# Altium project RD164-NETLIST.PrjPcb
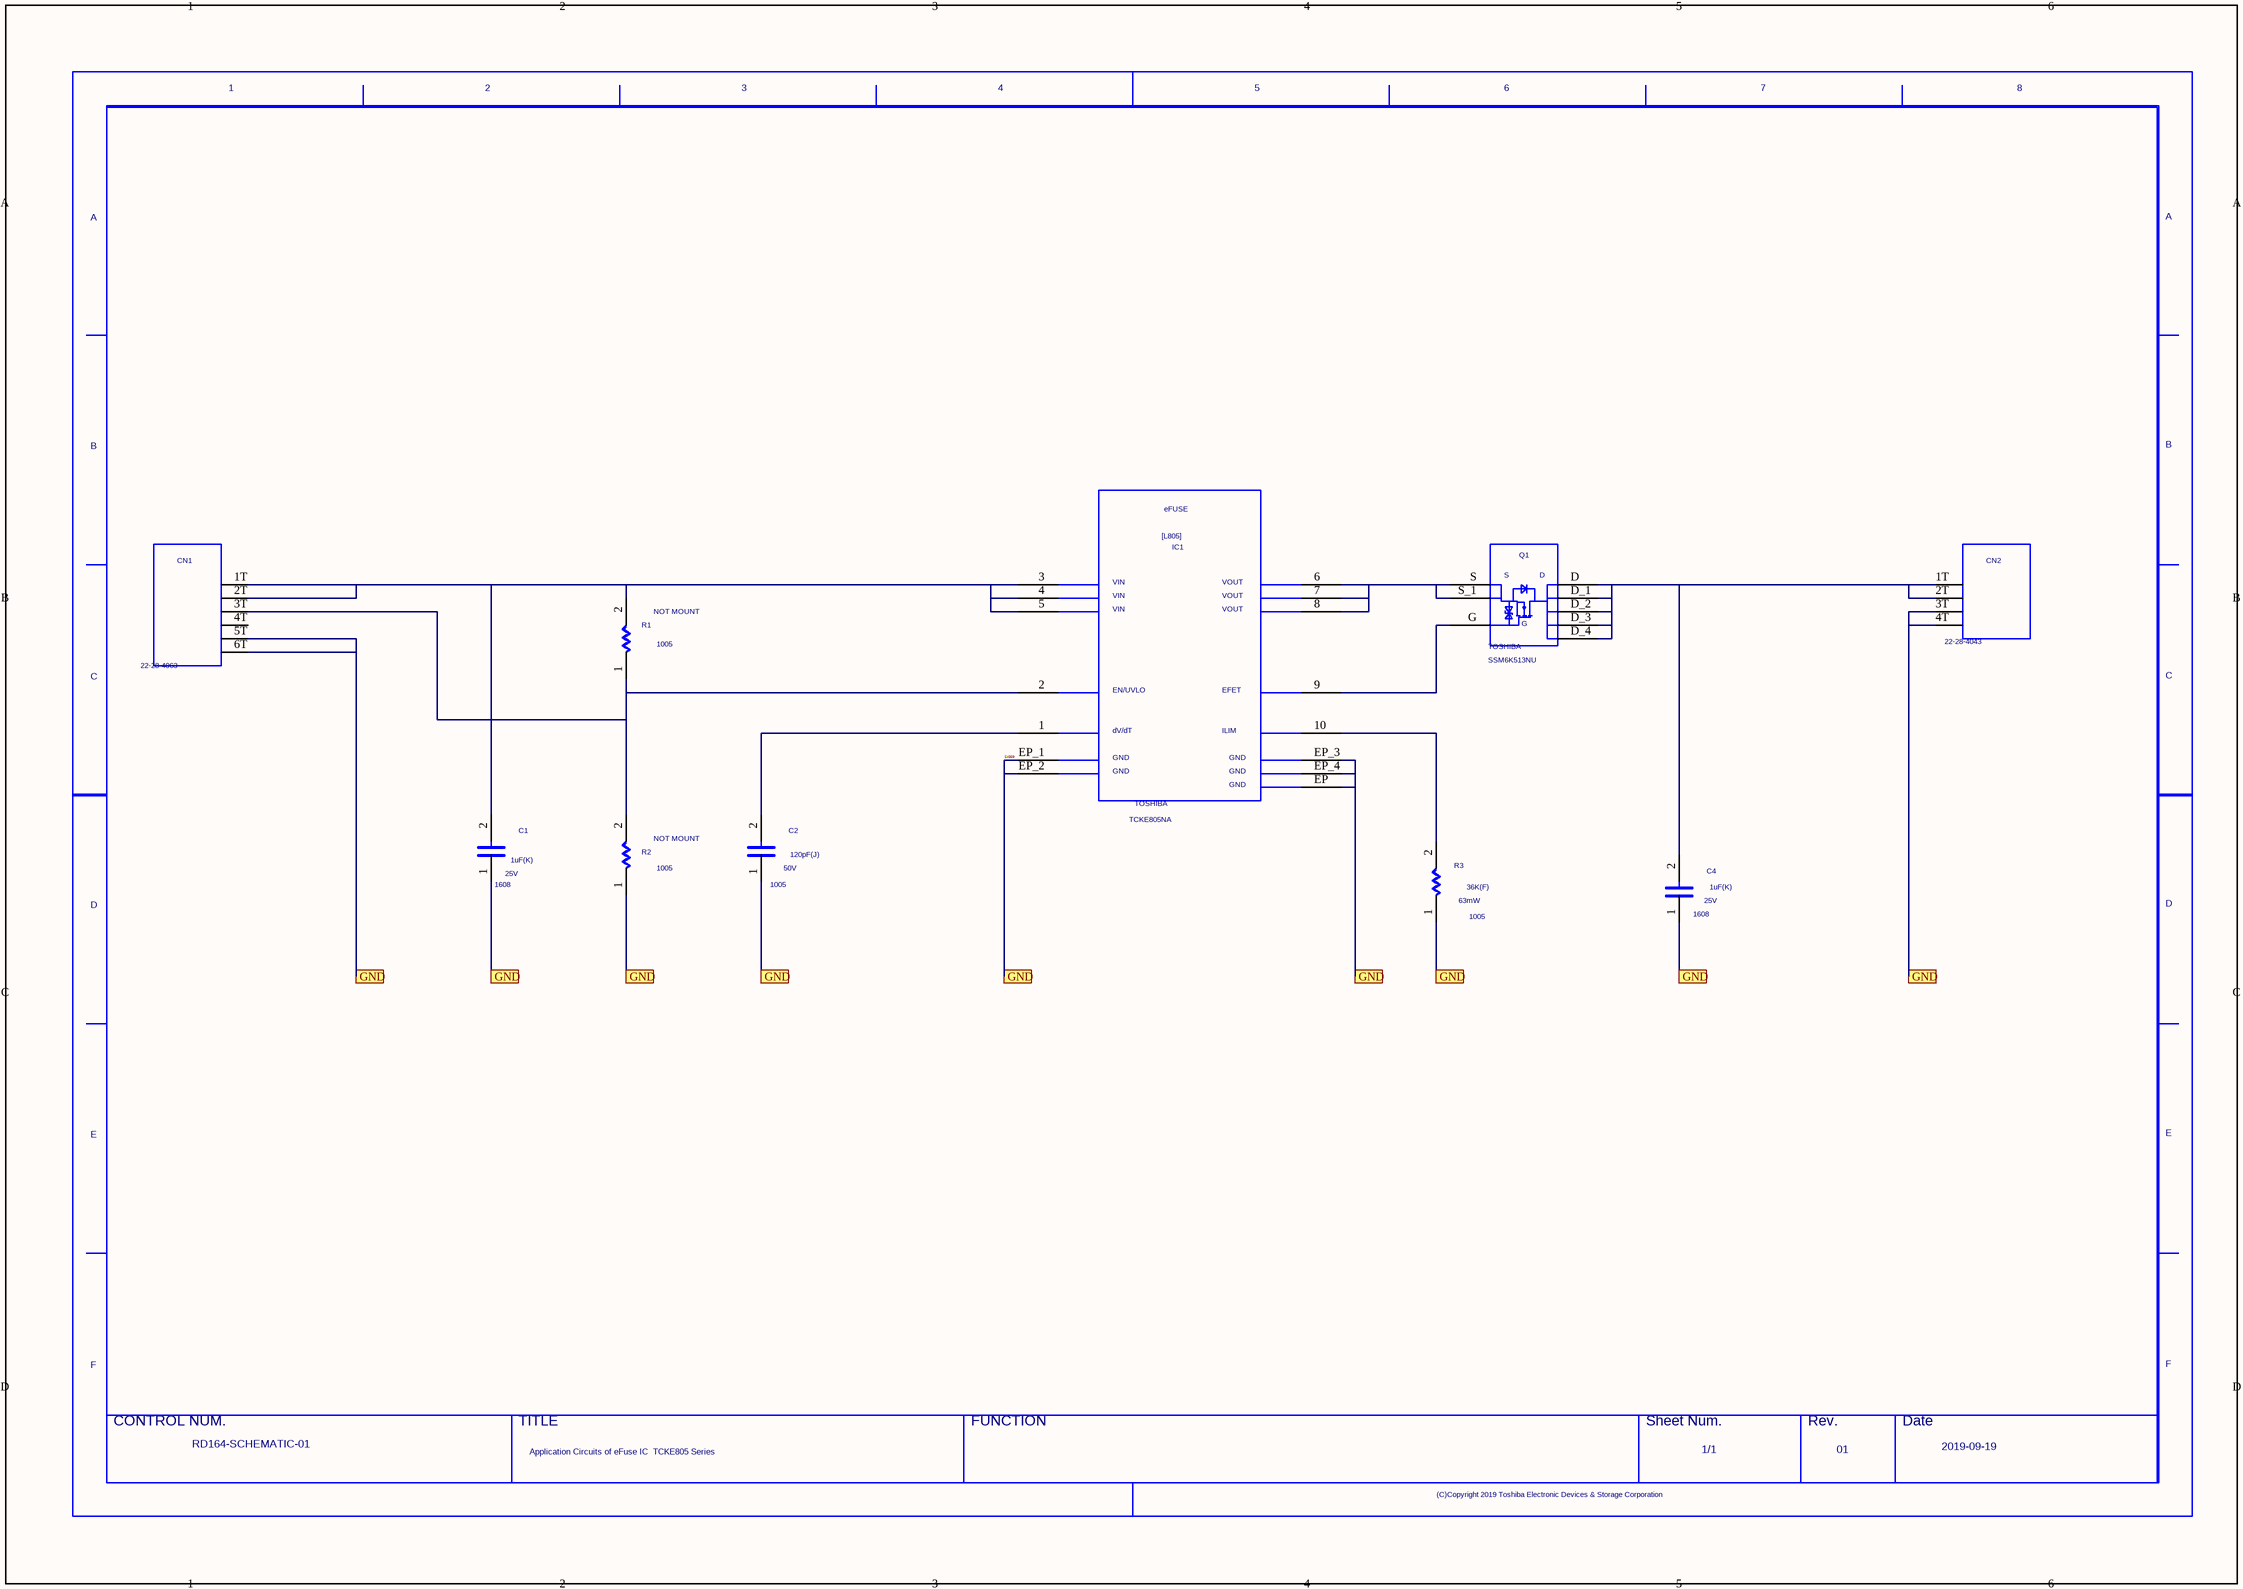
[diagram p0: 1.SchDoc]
1 sheet, 11 parts. Net scope: flat (ports and power ports of the same name join across sheets).

## Sheet 1.SchDoc
size 420 x 297 mm

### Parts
C1  SIZECODESMD: 1608  VAL2: 25V  VAL1: 1uF(K)  (hidden comment: C)
C2  SIZECODESMD: 1005  VAL2: 50V  VAL1: 120pF(J)  (hidden comment: C)
C4  SIZECODESMD: 1608  VAL2: 25V  VAL1: 1uF(K)  (hidden comment: C)
CN1  22-28-4063
CN2  22-28-4043
IC1  USERCOMPTEXT3: TOSHIBA  VAL3: TCKE805NA  (hidden comment: TCKE805)
Q1  USERCOMPTEXT3: TOSHIBA  VAL3: SSM6K513NU  (hidden comment: SSM6K513)
R1  NOTMOUNT: NOT MOUNT  SIZECODESMD: 1005  (hidden comment: R)
R2  NOTMOUNT: NOT MOUNT  SIZECODESMD: 1005  (hidden comment: R)
R3  SIZECODESMD: 1005  VAL2: 63mW  VAL1: 36K(F)  (hidden comment: R)
U?  DATE: 2019-09-19  REVISION: 01  SHEETNUMBER: 1/1  TITLE: Application Circuits of eFuse IC / TCKE805 Series  DRAWINGNUMBER: RD164-SCHEMATIC-01  (hidden comment: WAKU_DEF100)

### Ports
GND

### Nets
NETC1_2: C1.2 CN1.1T CN1.2T IC1.3 IC1.4 IC1.5 R1.2
NETC2_2: C2.2 IC1.1
NETC4_2: C4.2 CN2.1T CN2.2T Q1.D Q1.D_1 Q1.D_2 Q1.D_3 Q1.D_4
NETCN1_3T: CN1.3T IC1.2 R1.1 R2.2
NETIC1_6: IC1.6 IC1.7 IC1.8 Q1.S Q1.S_1
NETIC1_9: IC1.9 Q1.G
NETIC1_10: IC1.10 R3.2
SIG59: C1.1 C2.1 C4.1 CN1.5T CN1.6T CN2.3T CN2.4T IC1.EP IC1.EP_1 IC1.EP_2 IC1.EP_3 IC1.EP_4 R2.1 R3.1 ; port GND

Not connected (* = marked no-connect by the designer): CN1 4T

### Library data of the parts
C1 = C: PARTNAME: TAIYO_YUDEN_1608_1; OriginalSymbolOrigin: (2540,7620); COMPONENTNAME: GDM030001341_package; MAXGCOUNT: 1; FUNCTION: GDM030001341; VAL3: TMK107BJ105KA-T
C2 = C: PARTNAME: C1005_MURATA; OriginalSymbolOrigin: (2540,7620); COMPONENTNAME: K0300575_package; MAXGCOUNT: 1; FUNCTION: K0300575; VAL3: UMK105SL121JV-F
C4 = C: PARTNAME: TAIYO_YUDEN_1608; OriginalSymbolOrigin: (2540,7620); COMPONENTNAME: GDM030001341_package; MAXGCOUNT: 1; FUNCTION: GDM030001341; VAL3: TMK107BJ105KA-T
CN1 = 22-28-4063: PARTNAME: 2_54_6; SAVEAREA0: -13107,-601,32466,29460; SAVECOUNT: 23; TIME: 13:28:28; UPDATEUSER: cae; UPDATETIME: 16:00:22; OriginalSymbolOrigin: (2540,25400)
CN2 = 22-28-4043: PARTNAME: 2_54_4; SAVEAREA0: -8829,-843,28769,23958; SAVECOUNT: 23; TIME: 13:28:28; UPDATEUSER: cae; UPDATETIME: 15:59:12; OriginalSymbolOrigin: (2540,20320)
IC1 = TCKE805: PARTNAME: WSON10B; SAVEAREA0: -21400,-662,82488,64135; SAVECOUNT: 22; TIME: 17:55:46; UPDATEUSER: cae; UPDATETIME: 15:44:05; OriginalSymbolOrigin: (7620,60960)
Q1 = SSM6K513: SAVEAREA0: -9081,-242,36640,23504; TIME: 18:57:44; UPDATEUSER: cae; UPDATETIME: 16:12:40; SAVECOUNT: 16; OriginalSymbolOrigin: (7620,20320)
R1 = R: PARTNAME: R1005_PANA_2; OriginalSymbolOrigin: (5080,5080); COMPONENTNAME: GAS010000128_package; MAXGCOUNT: 1; FUNCTION: GAS010000128; VAL3: RK73Z1ETTP@@; VAL2: 0W; VAL1: 0(X)
R2 = R: PARTNAME: R1005_PANA_1; OriginalSymbolOrigin: (5080,5080); COMPONENTNAME: GAS010000128_package; MAXGCOUNT: 1; FUNCTION: GAS010000128; VAL3: RK73Z1ETTP@@; VAL2: 0W; VAL1: 0(X)
R3 = R: PARTNAME: R1005_PANA; OriginalSymbolOrigin: (5080,5080); COMPONENTNAME: G36010118220_package; MAXGCOUNT: 1; FUNCTION: G36010118220; VAL3: ERJ2RKF3602X
U? = WAKU_DEF100: PLOTTIME: HH:MM; SAVEAREA0: 198008,-65938,436964,90161; TIME: 14:30:25; UPDATEUSER: t5459927; UPDATETIME: 17:05:09; SAVECOUNT: 4; OriginalSymbolOrigin: (10160,284480)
